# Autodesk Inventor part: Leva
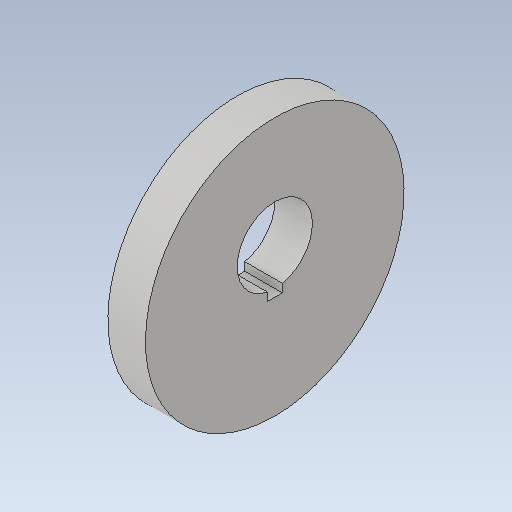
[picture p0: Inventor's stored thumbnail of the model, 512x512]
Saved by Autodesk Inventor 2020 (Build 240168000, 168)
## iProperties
Created: 2019-09
Part Number: Leva
Material: Generic
Document SubType Name: Modeling
Designer: user
Density: 1 g/cm^3
Appearance: Default
Mass: 4.24509 g
Surface Area: 24.0647 cm^2
Volume: 4.24509 cm^3
Author: user
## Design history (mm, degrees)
sketch "Sketch1"
  geometry: L1 (-4.899, 1)-(-6, 1); L2 (-6, 1)-(-6, -1); L3 (-6, -1)-(-4.899, -1); A1 r 17.202 centre (-2.5, 0) between (14.702, 0) and (-19.702, 0); A2 r 17.202 centre (-2.5, 0) between (-19.702, 0) and (14.702, 0); A3 r 5 centre (0, 0) between (-4.899, -1) and (-4.899, 1); 1 further point
  constraints: 6 end point, 6 point on circle, 3 centre point, 1 coincident, 1 concentric, 1 horizontal, 1 parallel, 1 perpendicular
  dimensions: "d2" = 10 diameter of A3
extrude "Extrusion1" new body sketch "Sketch1" distance "d3" = 5; taper "d4" = 0 deg
body "Solid1"
